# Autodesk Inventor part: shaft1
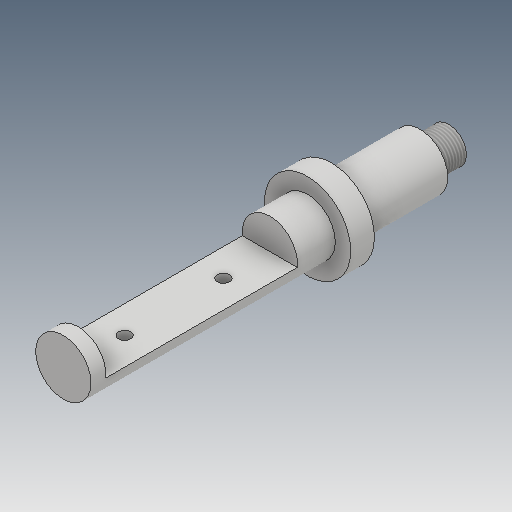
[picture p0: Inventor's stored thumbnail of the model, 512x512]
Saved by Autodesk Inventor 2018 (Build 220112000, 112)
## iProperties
Created: 2016-07
Part Number: shaft1
Material: Generic
Document SubType Name: Modeling
Designer: Sandeep
Density: 1 g/cm^3
Appearance: Default
Author: Sandeep
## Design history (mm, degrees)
sketch "Sketch1"
  geometry: L1 (-125.556, 0)-(92.286, 0); L2 (0, 18)-(28.9, 18); L3 (28.9, 18)-(28.9, 28); L4 (28.9, 28)-(118.7, 28); L5 (118.7, 28)-(118.7, 43.6); L6 (118.7, 43.6)-(142.7, 43.6); L7 (142.7, 43.6)-(142.7, 28); L8 (142.7, 28)-(389.8, 28); L9 (389.8, 28)-(389.8, 0); L10 (0, 18)-(0, 0); L11 (0, 0)-(389.8, 0)
  constraints: 22 end point, 7 perpendicular, 3 point on line, 2 horizontal, 1 collinear
  dimensions: "d0" = 36 diameter of L2 L1; "d1" = 56 diameter of L4 L1; "d2" = 87.2 diameter of L6 L1; "d3" = 28.9 distance between parallel lines of L3 L10; "d5" = 247.1 distance between parallel lines of L9 L7; "d6" = 24 distance between parallel lines of L5 L7; "d7" = 89.8 distance between parallel lines of L3 L5
revolve "Revolution1" sketch "Sketch1" stored, may be unused: angle "d8" = 90 deg
sketch "Sketch5"
  geometry: L1 (-142.7, 28)-(-389.8, 28) reference; L2 (-180.9, 28)-(-374.7, 28); L3 (-374.7, 28)-(-374.7, -3.1); L4 (-374.7, -3.1)-(-180.9, -3.1); L5 (-180.9, -3.1)-(-180.9, 28); L6 (-389.8, 28)-(-389.8, -28) reference; 1 further point
  constraints: 8 end point, 2 parallel, 1 horizontal, 1 perpendicular, 1 point on line
  dimensions: "d18" = 15.1 distance between parallel lines of L6 L3; "d19" = 193.8 distance between parallel lines of L5 L3; "d20" = 24.9 distance from line of L6.end L4
extrude "Extrusion3" cut sketch "Sketch5" stored distance "d21" = 62.5; taper "d22" = 0 deg
sketch "Sketch6"
  geometry: L1 (0, 0.172)-(0, -55.828) reference; L2 (208.9, -55.828)-(208.9, 0.172) reference; L3 (208.9, -27.828)-(-12.149, -27.828); C1 r 6.25 at (146.9, -27.828); C2 r 6.25 at (46.9, -27.828); 3 further points
  constraints: 2 centre point, 2 end point, 2 point on line, 1 equal radius, 1 horizontal, 1 midpoint
  dimensions: "d23" = 100 distance of C1.centre C2.centre; "d24" = 12.5 diameter of C2; "d25" = 46.9 distance from line of L1 C2.centre
extrude "Extrusion4" cut sketch "Sketch6" distance "d26" = 62.5; taper "d27" = 0 deg
thread "Thread1" dims "d28" = 10, "d29" = 0
sketch "Sketch9"
  geometry: L1 (-8, -26.833)-(-8, -22); L2 (-8, -22)-(8, -22); L3 (8, -22)-(8, -26.833); L4 (0, 0)-(0, -22.852); A1 r 28 centre (0, 0) between (8, -26.833) and (-8, -26.833) reference; 2 further points
  constraints: 8 end point, 3 point on circle, 1 parallel, 1 vertical, 1 other
  dimensions: "d34" = 16 distance between parallel lines of L1 L3; "d35" = 50 dimension on A1 L2
extrude "Extrusion5" cut sketch "Sketch9" distance "d36" = 66; taper "d37" = 0 deg
body "Solid1"
